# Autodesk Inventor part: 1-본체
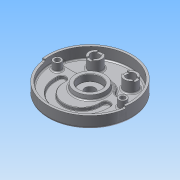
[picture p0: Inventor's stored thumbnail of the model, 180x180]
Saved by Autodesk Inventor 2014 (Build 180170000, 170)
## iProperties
Created: 2015-06
Part Number: 1-본체
Material: 알루미늄 6061
Document SubType Name: Modeling
Designer: Administrator
Density: 2.71 g/cm^3
Appearance: 알루미늄 - 평지
Mass: 1071.01 g
Surface Area: 1034.4 cm^2
Volume: 395.205 cm^3
Author: Administrator
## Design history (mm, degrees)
sketch "스케치1"
  geometry: C1 r 95 at (0, 0); 1 further point
  constraints: 1 centre point, 1 coincident
  dimensions: "d0" = 190 diameter of C1
extrude "돌출1" new body sketch "스케치1" distance "d1" = 32; taper "d2" = 0 deg
feature "쉘1" dims "d3" = 14, "d4" = 5
sketch "스케치2"
  geometry: L1 (-38.833, 16)-(-88.566, 16); L2 (38.833, 16)-(88.566, 16); A1 r 90 centre (0, 0) between (-88.566, 16) and (88.566, 16) reference; A2 r 42 centre (0, 0) between (38.833, 16) and (-38.833, 16)
  constraints: 4 end point, 4 point on circle, 2 collinear, 1 centre point, 1 coincident, 1 horizontal
  dimensions: "d5" = 84 diameter of A2; "d6" = 16 distance from line of L2 A1.centre
extrude "돌출2" cut sketch "스케치2" distance "d7" = 7; taper "d8" = 0 deg
sketch "스케치3"
  geometry: L1 (88.566, 16)-(38.833, 16) reference; L2 (-59, -19)-(-41, -19); L3 (41, -19)-(59, -19); L4 (-59, -14)-(-59, -19); L5 (-41, -14)-(-41, -19); L6 (41, -14)-(41, -19); L7 (59, -14)-(59, -19); A1 r 90 centre (0, 0) between (-88.566, 16) and (88.566, 16) reference; A2 r 41 centre (0, -19) between (-41, -19) and (41, -19); A3 r 59 centre (0, -19) between (-59, -19) and (59, -19); A4 r 9 centre (-50, -14) between (-41, -14) and (-59, -14); A5 r 9 centre (50, -14) between (59, -14) and (41, -14); 2 further points
  constraints: 12 end point, 10 point on circle, 4 centre point, 4 tangent, 3 parallel, 3 vertical alignment, 2 collinear, 2 midpoint, 1 concentric, 1 equal radius, 1 horizontal alignment, 1 point on line
  dimensions: "d9" = 19 distance of A2.centre A1.centre; "d11" = 41 radius of A2; "d13" = 59 radius of A3; "d14" = 18 diameter of A5; "d15" = 5 distance from line of L2 A4.centre
extrude "돌출3" cut sketch "스케치3" distance "d16" = 7; taper "d17" = 0 deg
sketch "스케치4"
  geometry: C1 r 35 at (0, 0); A1 r 42 centre (0, 0) between (38.833, 16) and (-38.833, 16) reference
  constraints: 1 centre point, 1 coincident
  dimensions: "d18" = 70 diameter of C1
extrude "돌출4" join sketch "스케치4" distance "d19" = 10; taper "d20" = -10 deg
sketch "스케치5"
  geometry: C1 r 35 at (0, 0) reference; C2 r 9 at (-74, 0); C3 r 9 at (74, 0); A1 r 90 centre (0, 0) between (-88.566, 16) and (88.566, 16) reference
  constraints: 2 centre point, 2 horizontal alignment, 1 equal radius
  dimensions: "d21" = 18 diameter of C3; "d22" = 148 distance of C3.centre C2.centre; "d23" = 74 distance of C1.centre C2.centre (= 0.5 x d22)
extrude "돌출5" join sketch "스케치5" stored distance "d24" = 7; taper "d25" = 0 deg
sketch "스케치6"
  geometry: C1 r 15 at (-40, 52); C2 r 15 at (40, 52); A1 r 42 centre (0, 0) between (38.833, 16) and (-38.833, 16) reference
  constraints: 2 centre point, 1 equal radius, 1 horizontal alignment
  dimensions: "d26" = 30 diameter of C2; "d27" = 80 distance of C2.centre C1.centre; "d28" = 52 vertical distance of A1.centre C2.centre; "d29" = 40 horizontal distance of A1.centre C1.centre (= 0.5 x d27)
extrude "돌출6" join sketch "스케치6" stored distance "d30" = 7; taper "d31" = 0 deg
sketch "스케치7"
  geometry: L1 (-6, 13.748)-(-6, -13.748); L2 (6, 13.748)-(6, -13.748); L3 (66.252, 6)-(93.748, 6); L4 (93.748, -6)-(66.252, -6); A1 r 15 centre (0, 0) between (-6, 13.748) and (-6, -13.748) reference; A2 r 15 centre (80, 0) between (66.252, 6) and (93.748, 6) reference; 1 further point
  constraints: 8 end point, 8 point on circle, 4 parallel, 1 perpendicular, 1 vertical
  dimensions: "d32" = 12 distance between parallel lines of L4 L3; "d33" = 12 distance between parallel lines of L2 L1
extrude "돌출7" cut sketch "스케치7" distance "d34" = 3; taper "d35" = 0 deg
sketch "스케치8"
  geometry: C1 r 15 at (-40, 52) reference; C2 r 15 at (40, 52) reference; 2 further points
  constraints: 2 coincident
hole "구멍1" sketch "스케치8" at (-40, 52), (40, 52) diameter "d36" = 20; stored, may be unused: countersink angle "d40" = 90 deg, drill point angle "d42" = 0 deg; dims "d37" = 6, "d38" = 4, "d39" = 2, "d41" = 8
sketch "스케치9"
  geometry: C1 r 95 at (0, 0) reference; C2 r 26 at (0, 0)
  constraints: 1 centre point, 1 coincident
  dimensions: "d43" = 52 diameter of C2
extrude "돌출8" join sketch "스케치9" distance "d44" = 12; taper "d45" = -15 deg
hole "구멍2" diameter "d48" = 23; stored, may be unused: countersink angle "d52" = 90 deg, drill point angle "d54" = 0 deg; dims "d46" = 10, "d47" = 10, "d49" = 6, "d50" = 50, "d51" = 15, "d53" = 8
sketch "스케치10"
  geometry: C1 r 9 at (-74, 0) reference; C2 r 9 at (74, 0) reference; 2 further points
  constraints: 2 coincident
hole "구멍3" sketch "스케치10" at (-74, 0), (74, 0) diameter "d55" = 11; stored, may be unused: countersink angle "d59" = 90 deg, drill point angle "d61" = 0 deg; dims "d56" = 6, "d57" = 18, "d58" = 11, "d60" = 8
sketch "스케치11"
  geometry: L1 (89.124, -12.526)-(94.075, -13.221); L2 (-89.124, -12.526)-(-94.075, -13.221); L3 (-95, 0)-(95, 0); A1 r 90 centre (0, 0) between (89.124, -12.526) and (-89.124, -12.526) reference; A2 r 95 centre (0, 0) between (94.075, -13.221) and (-94.075, -13.221) reference
  constraints: 6 end point, 6 point on circle, 1 equal length, 1 horizontal, 1 midpoint
  dimensions: "d62" = 8 deg angle of L3 L1; "d63" = 8 deg angle of L3 L2; "d64" = 0 distance from line of A2.centre L2
extrude "돌출9" cut sketch "스케치11" distance "d65" = 5; taper "d66" = 0 deg
fillet "모깎기1" dims "d67" = 1, "d68" = 10, "d69" = 0.3, "d75" = 5
fillet "모깎기2" dims "d70" = 3
fillet "모깎기3" dims "d71" = 3
chamfer "모따기1" distance "d72" = 1; stored, may be unused: second distance "d73" = 2, angle "d74" = 45 deg
sketch "스케치12"
  geometry: C1 r 28.302 at (0, 0) reference; C2 r 68 at (0, 0)
  constraints: 1 centre point, 1 coincident, 1 other
  dimensions: "d76" = 136 diameter of C2
feature "엠보싱1" sketch "스케치12" dims "d77" = 0.5, "d78" = 0
node "솔리드1"
node "투영된 루프1"
other parameters: "d12" = 59
